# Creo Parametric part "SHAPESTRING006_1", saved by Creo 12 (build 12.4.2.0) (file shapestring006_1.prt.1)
Units: Custom; MM, KILOGRAM, SECS

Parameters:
  PTC_WM_ITERATION = "0"
  PTC_WM_VERSION = "-.0"
  PTC_WM_LIFECYCLE_STATE = "In Work"
  PTC_WM_LIFECYCLE = "MO_CADDocument"
  PTC_WM_CREATED_BY = "Maximilian Roepper (Z0017RMS: MO)"
  PTC_WM_CREATED_ON = "18-Sep-26 11:36:42 AM"
  PTC_WM_MODIFIED_BY = "Maximilian Roepper (Z0017RMS: MO)"
  PTC_WM_MODIFIED_ON = "18-Sep-26 11:36:46 AM"
  PDMLINKNUMBER = "PDM000071455186"
  PTC_WM_NAME = "shapestring006_1.prt"
  PTC_WM_NUMBER = "PDM000071455186"

Other parameters: WEIGHT, WEIGHT_FACTOR, WEIGHT_ADD, _MASS_TEMP, _DIFF_TEMP, MC_ERRORS, SUPPLIER

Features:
  1. coordinate system
  2. datum plane "PRT_YZ"
  3. datum plane "PRT_XY"
  4. datum plane "PRT_XZ"
  5. coordinate system
  6. datum axis
  7. datum axis
  8. datum axis
  9. coordinate system
  10. imported feature
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
Other named items: PRT, SIEMENS_MO, DRW_VIEW_ORG, PRT_X, PRT_Y, PRT_Z, CS0, ROUGH_GROB

Layers: 00_STD_CSYS-KSYS, 01_STD_PLANES-EBENEN, 02_STD_AXES-ACHSEN, 03_STD_CSYS-KSYS, 24_IMPORT_FEAT-IMPORT_KE, WHITE

Surfaces: 1 plane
